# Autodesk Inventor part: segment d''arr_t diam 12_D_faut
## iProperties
Created: 2011-10
Part Number: segment d''arr_t diam 12_D_faut
Document SubType Name: Modeling
Designer: Bruno
Author: Bruno
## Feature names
1. Base1
